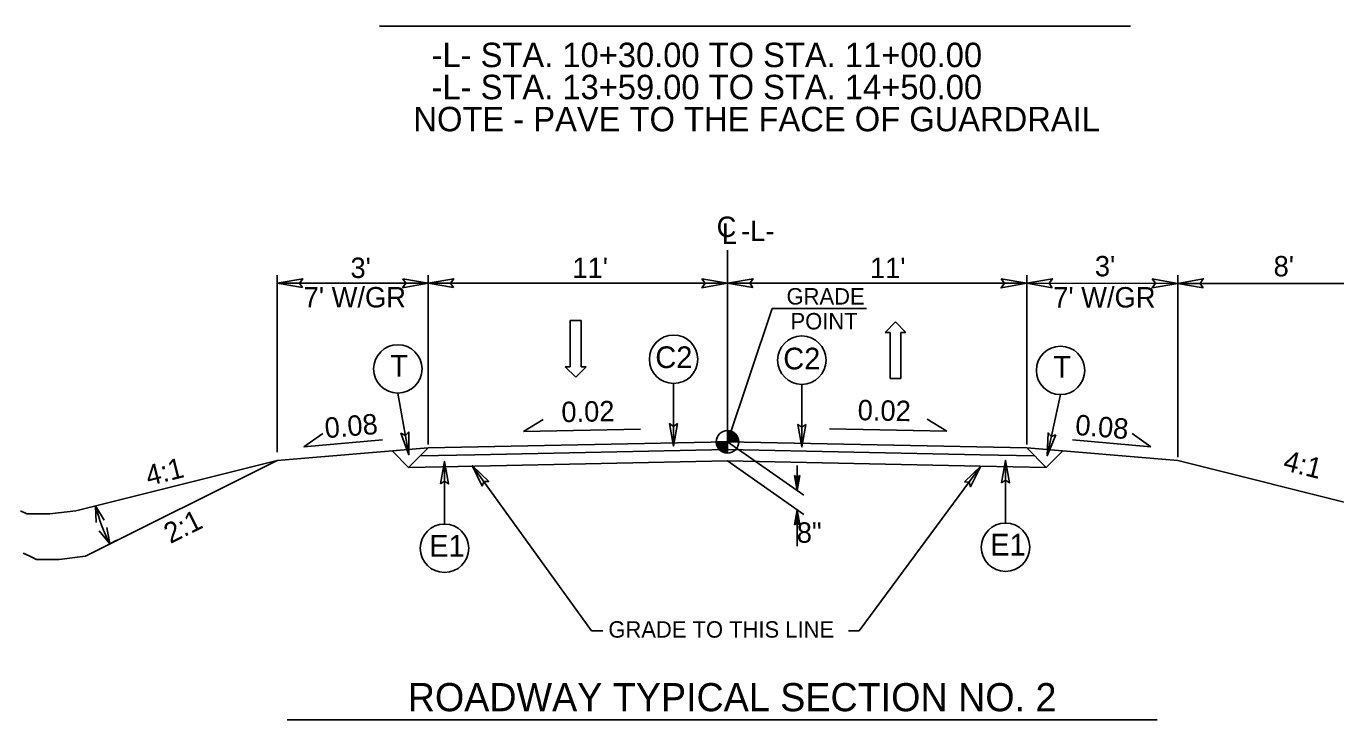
# Model space of a CAD drawing. Extents: x 573711 to 575883, y -54585 to -53485.
# Drawn here: x 574438.9 to 574921.1, y -54017.7 to -53762.5 of the extents above; entities that cross this region are included whole.
import ezdxf

# ---------------------------------------------------------------- set-up
doc = ezdxf.new("R2010")
doc.units = 0
for name, color, linetype in [('Old_Level_1', 7, 'Continuous'), ('Old_Level_11', 7, 'Continuous'), ('Old_Level_2', 7, 'Continuous'), ('Old_Level_20', 7, 'Continuous'), ('Old_Level_3', 7, 'Continuous'), ('Prop Lane Arrow CELL', 7, 'Continuous'), ('Typical Terminator CELL', 7, 'Continuous')]:
    doc.layers.add(name, color=color, linetype=linetype)

msp = doc.modelspace()

# ---------------------------------------------------------------- linework, layer by layer
at = {"layer": 'Old_Level_1'}
for p, q in [((574697.08, -53915.43), (574697.09, -53844.87)), ((574697.08, -53915.43), (574697.08, -53911.29)), ((574531.29, -53922.25), (574586.89, -53917.63)), ((574579.7, -53924.81), (574586.89, -53917.63)), ((574586.89, -53917.63), (574697.08, -53915.43)), ((574692.94, -53915.43), (574697.08, -53915.43)), ((574697.07, -53919.58), (574697.08, -53915.43)), ((574697.08, -53915.43), (574697.07, -53919.58)), ((574807.28, -53917.65), (574697.08, -53915.43)), ((574701.23, -53915.43), (574697.08, -53915.43)), ((574697.08, -53915.43), (574725.18, -53935.11)), ((574807.28, -53917.65), (574814.46, -53924.83)), ((574862.87, -53922.28), (574807.28, -53917.65)), ((574531.29, -53922.25), (574457.17, -53940.78)), ((574460.68, -53957.55), (574531.29, -53922.25)), ((574573.62, -53918.73), (574579.7, -53924.81)), ((574583.96, -53920.55), (574604.05, -53920.15)), ((574604.04, -53924.33), (574697.08, -53922.47)), ((574604.05, -53920.15), (574697.08, -53918.3)), ((574790.14, -53920.17), (574697.08, -53918.3)), ((574790.14, -53924.34), (574697.08, -53922.47)), ((574697.09, -53922.47), (574725.18, -53942.15)), ((574810.2, -53920.57), (574790.14, -53920.17)), ((574814.46, -53924.83), (574820.54, -53918.75)), ((574862.87, -53922.28), (574936.99, -53940.82)), ((574579.7, -53924.81), (574604.04, -53924.33)), ((574722.72, -53924.1), (574722.72, -53933.38)), ((574814.46, -53924.83), (574790.14, -53924.34)), ((574722.72, -53933.38), (574721.75, -53927.86)), ((574722.72, -53928.58), (574721.75, -53927.86)), ((574722.72, -53933.38), (574721.88, -53927.96)), ((574722.02, -53928.07), (574722.72, -53933.38)), ((574722.72, -53933.38), (574722.16, -53928.17)), ((574722.3, -53928.27), (574722.72, -53933.38)), ((574722.72, -53933.38), (574722.44, -53928.37)), ((574722.58, -53928.47), (574722.72, -53933.38)), ((574722.72, -53933.38), (574723.69, -53927.86)), ((574723.69, -53927.86), (574722.72, -53928.58)), ((574723.55, -53927.96), (574722.72, -53933.38)), ((574722.72, -53933.38), (574723.41, -53928.07)), ((574723.27, -53928.17), (574722.72, -53933.38)), ((574722.72, -53933.38), (574723.13, -53928.27)), ((574723, -53928.37), (574722.72, -53933.38)), ((574722.72, -53933.38), (574722.86, -53928.47)), ((574722.72, -53928.58), (574722.72, -53933.38)), ((574722.72, -53940.43), (574721.74, -53945.96)), ((574721.88, -53945.85), (574722.72, -53940.43)), ((574722.72, -53940.43), (574722.02, -53945.75)), ((574722.16, -53945.64), (574722.72, -53940.43)), ((574722.72, -53940.43), (574722.3, -53945.54)), ((574722.44, -53945.45), (574722.72, -53940.43)), ((574722.72, -53940.43), (574722.57, -53945.34)), ((574722.72, -53940.43), (574722.72, -53953.78)), ((574722.72, -53940.43), (574723.69, -53945.96)), ((574722.72, -53945.24), (574722.72, -53940.43)), ((574722.86, -53945.34), (574722.72, -53940.43)), ((574722.72, -53940.43), (574722.99, -53945.45)), ((574723.13, -53945.54), (574722.72, -53940.43)), ((574722.72, -53940.43), (574723.27, -53945.64)), ((574723.41, -53945.75), (574722.72, -53940.43)), ((574722.72, -53940.43), (574723.55, -53945.85)), ((574721.74, -53945.96), (574722.72, -53945.24)), ((574722.72, -53945.24), (574723.69, -53945.96))]:
    msp.add_line(p, q, dxfattribs=at)
for points in [[(574697.12, -53911.29), (574697.12, -53911.29), (574697.12, -53915.43)], [(574697.2, -53911.29), (574697.2, -53915.43)], [(574697.29, -53911.29), (574697.29, -53915.43)], [(574697.37, -53911.3), (574697.37, -53915.43)], [(574697.45, -53911.3), (574697.45, -53915.43)], [(574697.54, -53911.31), (574697.53, -53915.43)], [(574697.62, -53911.32), (574697.62, -53915.43)], [(574697.7, -53911.33), (574697.7, -53915.43)], [(574697.78, -53911.34), (574697.78, -53915.43)], [(574697.87, -53911.36), (574697.87, -53915.43)], [(574697.95, -53911.38), (574697.95, -53915.43)], [(574698.03, -53911.4), (574698.03, -53915.43)], [(574698.12, -53911.41), (574698.12, -53915.43)], [(574698.2, -53911.44), (574698.2, -53915.43)], [(574698.28, -53911.46), (574698.28, -53915.43)], [(574698.36, -53911.49), (574698.36, -53915.43)], [(574698.45, -53911.52), (574698.45, -53915.43)], [(574698.53, -53911.54), (574698.53, -53915.43)], [(574698.61, -53911.58), (574698.61, -53915.43)], [(574698.7, -53911.62), (574698.7, -53915.43)], [(574698.78, -53911.65), (574698.78, -53915.43)], [(574698.86, -53911.69), (574698.86, -53915.43)], [(574698.95, -53911.73), (574698.95, -53915.43)], [(574699.03, -53911.77), (574699.03, -53915.43)], [(574699.11, -53911.82), (574699.11, -53915.43)], [(574699.19, -53911.87), (574699.19, -53915.43)], [(574699.28, -53911.91), (574699.28, -53915.43)], [(574699.36, -53911.97), (574699.36, -53915.43)], [(574699.44, -53912.02), (574699.44, -53915.43)], [(574699.53, -53912.09), (574699.53, -53915.43)], [(574699.61, -53912.14), (574699.61, -53915.43)], [(574699.69, -53912.21), (574699.69, -53915.43)], [(574699.77, -53912.28), (574699.77, -53915.43)], [(574699.86, -53912.35), (574699.86, -53915.43)], [(574699.94, -53912.43), (574699.94, -53915.43)], [(574700.02, -53912.51), (574700.02, -53915.43)], [(574700.11, -53912.59), (574700.11, -53915.43)], [(574700.19, -53912.69), (574700.19, -53915.43)], [(574700.27, -53912.79), (574700.27, -53915.43)], [(574700.36, -53912.89), (574700.36, -53915.43)], [(574692.95, -53915.43), (574692.95, -53915.88)], [(574693.04, -53915.43), (574693.04, -53916.37)], [(574693.12, -53915.43), (574693.12, -53916.67)], [(574693.2, -53915.43), (574693.2, -53916.92)], [(574693.29, -53915.43), (574693.29, -53917.11)], [(574693.37, -53915.43), (574693.37, -53917.29)], [(574693.45, -53915.43), (574693.45, -53917.44)], [(574693.53, -53915.43), (574693.53, -53917.59)], [(574693.62, -53915.43), (574693.62, -53917.72)], [(574693.7, -53915.43), (574693.7, -53917.84)], [(574693.78, -53915.43), (574693.78, -53917.95)], [(574693.87, -53915.43), (574693.87, -53918.05)], [(574693.95, -53915.43), (574693.95, -53918.15)], [(574694.03, -53915.43), (574694.03, -53918.24)], [(574694.11, -53915.43), (574694.11, -53918.34)], [(574694.2, -53915.43), (574694.2, -53918.42)], [(574694.28, -53915.43), (574694.28, -53918.49)], [(574694.36, -53915.43), (574694.36, -53918.57)], [(574694.45, -53915.43), (574694.45, -53918.64)], [(574694.53, -53915.43), (574694.53, -53918.71)], [(574694.61, -53915.43), (574694.61, -53918.77)], [(574694.7, -53915.43), (574694.7, -53918.83)], [(574694.78, -53915.43), (574694.78, -53918.88)], [(574694.86, -53915.43), (574694.86, -53918.94)], [(574694.94, -53915.43), (574694.94, -53918.99)], [(574695.03, -53915.43), (574695.03, -53919.04)], [(574695.11, -53915.43), (574695.11, -53919.08)], [(574695.19, -53915.43), (574695.19, -53919.13)], [(574695.28, -53915.43), (574695.28, -53919.17)], [(574695.36, -53915.43), (574695.36, -53919.2)], [(574695.44, -53915.43), (574695.44, -53919.24)], [(574695.53, -53915.43), (574695.52, -53919.28)], [(574695.61, -53915.43), (574695.61, -53919.31)], [(574695.69, -53915.43), (574695.69, -53919.34)], [(574695.77, -53915.43), (574695.77, -53919.37)], [(574695.86, -53915.43), (574695.86, -53919.4)], [(574695.94, -53915.43), (574695.94, -53919.42)], [(574696.02, -53915.43), (574696.02, -53919.44)], [(574696.11, -53915.43), (574696.11, -53919.46)], [(574696.19, -53915.43), (574696.19, -53919.48)], [(574696.27, -53915.43), (574696.27, -53919.5)], [(574696.35, -53915.43), (574696.35, -53919.52)], [(574696.44, -53915.43), (574696.44, -53919.53)], [(574696.52, -53915.43), (574696.52, -53919.54)], [(574696.6, -53915.43), (574696.6, -53919.55)], [(574696.69, -53915.43), (574696.69, -53919.56)], [(574696.77, -53915.43), (574696.77, -53919.57)], [(574696.85, -53915.43), (574696.85, -53919.57)], [(574696.94, -53915.43), (574696.94, -53919.58)], [(574697.02, -53915.43), (574697.02, -53919.58), (574697.02, -53919.58)], [(574700.44, -53913), (574700.44, -53915.43)], [(574700.52, -53913.12), (574700.52, -53915.43)], [(574700.6, -53913.25), (574700.6, -53915.43)], [(574700.69, -53913.39), (574700.69, -53915.43)], [(574700.77, -53913.53), (574700.77, -53915.43)], [(574700.85, -53913.71), (574700.85, -53915.43)], [(574700.94, -53913.9), (574700.94, -53915.43)], [(574701.02, -53914.13), (574701.02, -53915.43)], [(574701.1, -53914.42), (574701.1, -53915.43)], [(574701.19, -53914.84), (574701.18, -53915.43)], [(574457.17, -53940.78), (574447.55, -53941.97), (574445.15, -53941.97), (574441.54, -53941.97), (574439.14, -53941.97), (574436.74, -53940.78)], [(574460.68, -53957.55), (574451.07, -53958.75), (574448.66, -53958.75), (574445.05, -53958.75), (574442.65, -53958.75), (574440.25, -53957.55), (574437.84, -53956.35)]]:
    msp.add_lwpolyline(points, dxfattribs=at)
msp.add_circle((574697.08, -53915.43), 4.15, dxfattribs=at)
for start, end in [(359.9851, 89.9851), (179.9851, 269.9851)]:
    msp.add_arc((574697.08, -53915.43), 4.15, start, end, dxfattribs=at)
at = {"layer": 'Old_Level_11'}
for p, q in [((574569.02, -53762.45), (574845.49, -53762.48)), ((574531.29, -53919.25), (574531.3, -53854.05)), ((574531.29, -53919.25), (574531.3, -53854.05)), ((574586.89, -53914.63), (574586.89, -53854.06)), ((574586.89, -53914.63), (574586.89, -53854.06)), ((574807.28, -53914.65), (574807.29, -53854.08)), ((574807.28, -53914.65), (574807.29, -53854.08)), ((574862.87, -53919.28), (574862.88, -53854.08)), ((574862.87, -53919.28), (574862.88, -53854.08)), ((574531.3, -53857.05), (574586.89, -53857.06)), ((574586.89, -53916.42), (574586.89, -53855.38)), ((574586.89, -53857.06), (574697.09, -53857.07)), ((574807.29, -53857.08), (574697.09, -53857.07)), ((574807.28, -53916.44), (574807.29, -53855.4)), ((574807.28, -53916.44), (574807.29, -53855.82)), ((574862.88, -53857.09), (574807.29, -53857.08)), ((574862.87, -53921.08), (574862.88, -53855.82)), ((574862.88, -53857.09), (574937, -53857.09)), ((574575.72, -53897.5), (574579.79, -53920.17)), ((574677.26, -53893.95), (574677.26, -53916.98)), ((574724.48, -53894.27), (574724.48, -53917.31)), ((574819.73, -53898.04), (574814.83, -53920.55)), ((574799.46, -53945.3), (574799.46, -53922.27)), ((574592.9, -53945.69), (574592.9, -53922.62)), ((574469.74, -53952.95), (574472.33, -53951.65)), ((574535, -54017.7), (574855.36, -54017.73))]:
    msp.add_line(p, q, dxfattribs=at)
for points in [[(574579.73, -53911.8), (574579.79, -53920.17), (574576.88, -53912.26), (574578.51, -53913.04)], [(574678.68, -53908.73), (574677.26, -53916.98), (574675.8, -53908.69), (574677.26, -53909.74)], [(574725.9, -53909.05), (574724.48, -53917.31), (574723.01, -53909.01), (574724.48, -53910.06)], [(574817.97, -53912.79), (574814.83, -53920.55), (574815.16, -53912.13), (574816.37, -53913.47)], [(574798.03, -53930.52), (574799.46, -53922.27), (574800.92, -53930.56), (574799.46, -53929.51)], [(574591.48, -53930.87), (574592.9, -53922.62), (574594.37, -53930.92), (574592.9, -53929.86)], [(574606.83, -53931.72), (574603.16, -53924.19), (574609.2, -53930.07), (574607.39, -53930.07)], [(574784.31, -53930.19), (574790.37, -53924.42), (574786.6, -53931.95), (574786.05, -53930.23)]]:
    msp.add_lwpolyline(points, close=True, dxfattribs=at)
for points in [[(574464.7, -53945.16), (574464.42, -53938.98), (574467.57, -53944.3)], [(574468.56, -53946.9), (574469.65, -53952.99), (574465.82, -53948.13)]]:
    msp.add_lwpolyline(points, dxfattribs=at)
for centre in [(574677.26, -53885.04), (574724.48, -53885.36), (574575.72, -53888.59), (574819.73, -53889.13), (574592.91, -53954.6), (574799.46, -53954.21)]:
    msp.add_circle(centre, 8.91, dxfattribs=at)
msp.add_arc((574531.09, -53922.18), 68.74, 194.187, 206.6371, dxfattribs=at)
at = {"layer": 'Old_Level_2'}
for p, q in [((574621.95, -53911.61), (574629.2, -53907.22)), ((574777.89, -53911.47), (574770.63, -53907.09)), ((574541.18, -53917.23), (574548.12, -53912.37)), ((574621.95, -53911.61), (574665.13, -53910.75)), ((574777.89, -53911.47), (574734.7, -53910.61)), ((574853, -53917.23), (574846.06, -53912.37)), ((574541.18, -53917.23), (574570.08, -53914.69)), ((574853, -53917.23), (574824.1, -53914.69))]:
    msp.add_line(p, q, dxfattribs=at)
at = {"layer": 'Old_Level_3'}
for p, q in [((574697.08, -53915.43), (574713.57, -53866.34)), ((574713.57, -53866.34), (574748.26, -53866.34)), ((574603.16, -53924.19), (574647.09, -53984.94)), ((574790.37, -53924.42), (574745.55, -53984.94)), ((574647.09, -53984.94), (574651.21, -53984.94)), ((574741.69, -53984.94), (574745.55, -53984.94))]:
    msp.add_line(p, q, dxfattribs=at)
at = {"layer": 'Prop Lane Arrow CELL'}
for p, q in [((574639.21, -53887.81), (574639.21, -53870.8)), ((574639.21, -53870.8), (574643.22, -53870.8)), ((574643.22, -53870.8), (574643.22, -53887.81)), ((574755.14, -53875.14), (574758.91, -53871.31)), ((574758.91, -53871.31), (574762.8, -53875.14)), ((574756.97, -53875.14), (574755.14, -53875.14)), ((574756.97, -53892.15), (574756.97, -53875.14)), ((574762.8, -53875.14), (574760.98, -53875.14)), ((574760.98, -53875.14), (574760.98, -53892.15)), ((574641.28, -53891.64), (574637.39, -53887.81)), ((574637.39, -53887.81), (574639.21, -53887.81)), ((574645.04, -53887.81), (574641.28, -53891.64)), ((574643.22, -53887.81), (574645.04, -53887.81)), ((574760.98, -53892.15), (574756.97, -53892.15))]:
    msp.add_line(p, q, dxfattribs=at)
at = {"layer": 'Typical Terminator CELL'}
for points in [[(574540.67, -53858.67), (574531.3, -53857.05), (574540.72, -53855.39), (574539.53, -53857.06)], [(574577.52, -53855.44), (574586.89, -53857.06), (574577.47, -53858.73), (574578.66, -53857.06)], [(574596.26, -53858.67), (574586.89, -53857.06), (574596.32, -53855.39), (574595.12, -53857.06)], [(574687.72, -53855.45), (574697.09, -53857.07), (574687.66, -53858.74), (574688.86, -53857.07)], [(574706.46, -53858.68), (574697.09, -53857.07), (574706.51, -53855.4), (574705.32, -53857.07)], [(574797.91, -53855.47), (574807.29, -53857.08), (574797.86, -53858.75), (574799.06, -53857.08)], [(574816.66, -53858.7), (574807.29, -53857.08), (574816.71, -53855.41), (574815.51, -53857.08)], [(574853.51, -53855.47), (574862.88, -53857.09), (574853.45, -53858.75), (574854.65, -53857.08)], [(574872.25, -53858.7), (574862.88, -53857.09), (574872.3, -53855.42), (574871.11, -53857.09)]]:
    msp.add_lwpolyline(points, close=True, dxfattribs=at)

# ---------------------------------------------------------------- texts
at = {"layer": 'Old_Level_1'}
for s, p in [('  -L- STA. 10+30.00 TO STA. 11+00.00', (574581.47, -53777.53)), ('  -L- STA. 13+59.00 TO STA. 14+50.00 ', (574581.47, -53789.33)), ('NOTE - PAVE TO THE FACE OF GUARDRAIL', (574581.47, -53801.13))]:
    msp.add_text(s, height=9, dxfattribs=at).set_placement(p)
for s, rotation, p in [('4:1', 14.0309, (574483.95, -53931.73)), ('4:1', 345.9584, (574901.31, -53925.73)), ('2:1', 26.5607, (574492, -53953.07)), (' 8" ', 360, (574719.82, -53952.58))]:
    msp.add_text(s, height=7.513, rotation=rotation, dxfattribs=at).set_placement(p)
at = {"layer": 'Old_Level_11'}
for s, height, rotation, p in [('C', 7.51, 359.9946, (574693.11, -53840.03)), ('L', 7.51, 359.9415, (574694.98, -53842.56)), ('-L-', 7.513, 359.9946, (574702.12, -53841.53)), ("3'", 7.513, 359.9946, (574558.29, -53855.13)), ("11'", 7.513, 359.9946, (574640.01, -53855.14)), ("11'", 7.513, 359.9946, (574749.57, -53855.15)), ("3'", 7.513, 359.9946, (574832.37, -53854.52)), ("8'", 7.513, 359.9946, (574898.18, -53854.53)), ("7' W/GR", 7.513, 359.9946, (574541.07, -53865.96)), ("7' W/GR", 7.513, 359.9946, (574817.05, -53865.99))]:
    msp.add_text(s, height=height, rotation=rotation, dxfattribs=at).set_placement(p)
at = {"layer": 'Old_Level_20'}
for s, height, p in [('T', 7.98, (574572.92, -53891.45)), ('C2', 7.977, (574670.53, -53888.27)), ('C2', 7.977, (574717.64, -53888.76)), ('T', 7.98, (574817.04, -53891.8)), ('E1', 7.977, (574587.28, -53957.66)), ('E1', 7.977, (574793.83, -53957.26))]:
    msp.add_text(s, height=height, dxfattribs=at).set_placement(p)
at = {"layer": 'Old_Level_3'}
for s, height, rotation, p in [('GRADE', 6.046, 359.9946, (574718.85, -53864.89)), ('POINT', 6.046, 359.9946, (574720.31, -53874.05)), ('0.02 ', 7.513, 1.1404, (574636.01, -53908.21)), ('0.02 ', 7.513, 358.8489, (574744.98, -53907.45)), ('0.08', 7.513, 4.7561, (574549.11, -53914.11)), ('0.08', 7.513, 355.2332, (574824.92, -53912.83)), ('ROADWAY TYPICAL SECTION NO. 2', 10.3693, 359.9946, (574579.38, -54014.57))]:
    msp.add_text(s, height=height, rotation=rotation, dxfattribs=at).set_placement(p)
msp.add_text('GRADE TO THIS LINE', height=6.0464, dxfattribs=at).set_placement((574653.25, -53987.49))

doc.saveas('drawing.dxf')
